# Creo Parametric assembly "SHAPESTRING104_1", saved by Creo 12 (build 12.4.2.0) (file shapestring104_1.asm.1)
Units: Custom; MM, KILOGRAM, SECS

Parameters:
  PTC_WM_ITERATION = "0"
  PTC_WM_VERSION = "-.0"
  PTC_WM_LIFECYCLE_STATE = "In Work"
  PTC_WM_LIFECYCLE = "MO_CADDocument"
  PTC_WM_CREATED_BY = "Maximilian Roepper (Z0017RMS: MO)"
  PTC_WM_CREATED_ON = "18-Sep-26 11:36:42 AM"
  PTC_WM_MODIFIED_BY = "Maximilian Roepper (Z0017RMS: MO)"
  PTC_WM_MODIFIED_ON = "18-Sep-26 11:36:46 AM"
  PDMLINKNUMBER = "PDM000071455067"
  PTC_WM_NAME = "shapestring104_1.asm"
  PTC_WM_NUMBER = "PDM000071455067"

Other parameters: WEIGHT, WEIGHT_FACTOR, WEIGHT_ADD, MC_ERRORS, SUPPLIER, ISPOSITIONINGASSEMBLY

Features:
  1. coordinate system
  2. imported feature
  3. component "SHAPESTRING102_1"
  4. component "SHAPESTRING103_1"

Other named items: DRW_VIEW_ORG, ROUGH-GROB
